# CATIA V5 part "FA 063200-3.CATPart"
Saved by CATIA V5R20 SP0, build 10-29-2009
Part number: FA 063200-3
Revision: ANY
Definition: UNKNOWN
Nomenclature: FA 063200-3
Source: Unknown
Bounding box of the stored display mesh (mm): x -2.109 to 2.109, y -2.45 to 2.45, z -2 to 2
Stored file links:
  C:\Users\Utente\Desktop\IO LAVORO\3D X SITO CF\CUMSA\3D files FA\FA 0632SF\FA 063200-3.CATPart

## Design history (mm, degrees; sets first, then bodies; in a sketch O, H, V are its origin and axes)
Body1 "Chaflán4" (main body)
  Solid1: solid without history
